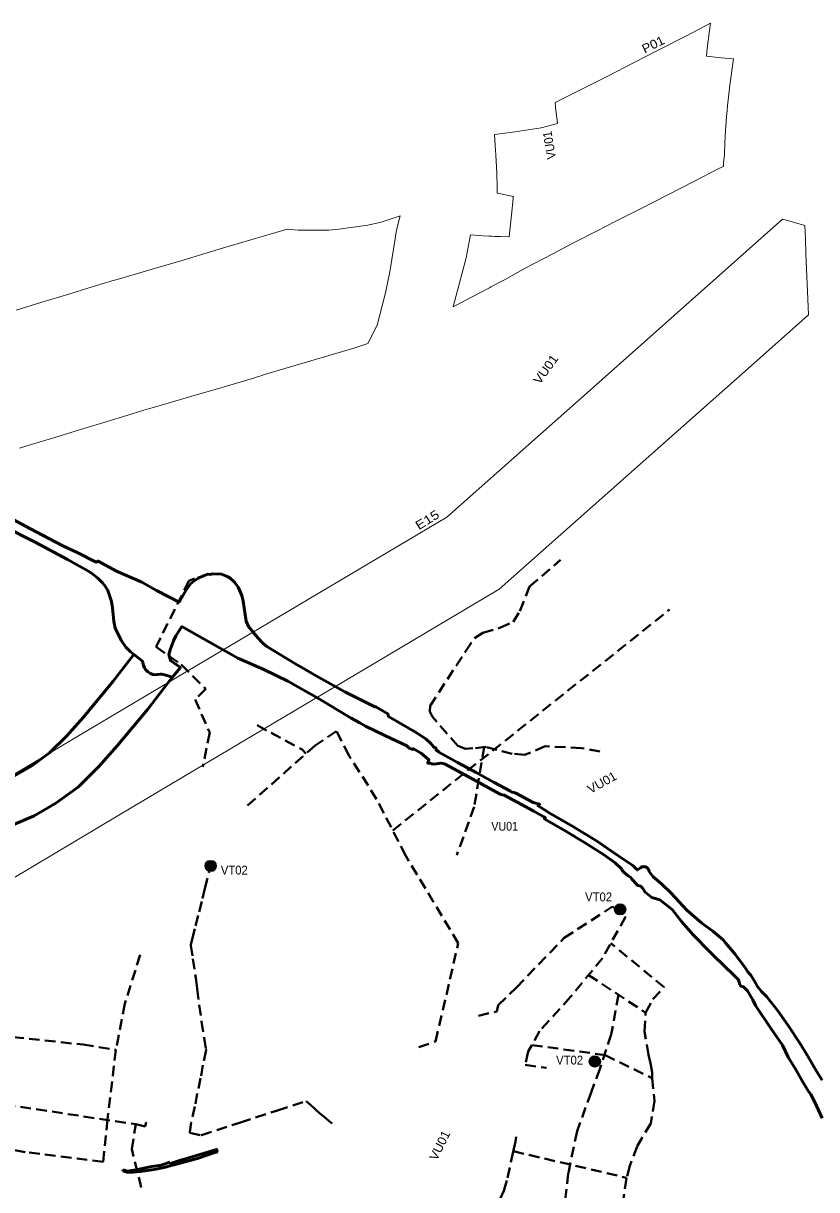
# Model space of a CAD drawing. Extents: x -650145 to -642675, y -1074338 to -1066724.
# Drawn here: x -646953 to -645166, y -1069896 to -1067267 of the extents above; entities that cross this region are included whole.
import ezdxf

# ---------------------------------------------------------------- set-up
doc = ezdxf.new("R2010")
doc.units = 0
doc.header["$LTSCALE"] = 8
doc.linetypes.add('MEDIUM_DASHED', pattern=[4.5, 3, -1.5])
for name, color, linetype, lineweight in [('12', 7, 'MEDIUM_DASHED', 40), ('15', 7, 'Continuous', 13), ('20', 7, 'Continuous', 13), ('44', 7, 'Continuous', 53), ('45', 7, 'Continuous', 53)]:
    doc.layers.add(name, color=color, linetype=linetype, lineweight=lineweight)
doc.layers.add('17', color=7, linetype='Continuous')
doc.layers.add('2', color=7, linetype='Continuous')

msp = doc.modelspace()

# ---------------------------------------------------------------- hatches: boundary and pattern name
at = {"layer": '15'}
for points in [[(-646519.621, -1069166.048, 1), (-646543.146, -1069166.048, 1)], [(-645597.068, -1069264.181, 1), (-645620.593, -1069264.181, 1)], [(-645654.023, -1069606.85, 1), (-645677.548, -1069606.85, 1)]]:
    msp.add_hatch(color=256, dxfattribs=at).paths.add_polyline_path(points)

# ---------------------------------------------------------------- linework, layer by layer
at = {"layer": '12'}
for p, q in [((-646121.289, -1069086.031), (-645497.437, -1068588.325)), ((-645679.959, -1069412.046), (-645551.493, -1069496.874)), ((-645849.328, -1069809.196), (-645594.304, -1069869.281))]:
    msp.add_line(p, q, dxfattribs=at)
for points in [[(-645654.382, -1068908.587), (-645695.934, -1068900.379), (-645777.633, -1068896.262), (-645823.286, -1068915.717), (-645852.103, -1068913.393), (-645911.131, -1068898.055), (-645940.704, -1068901.002), (-645957.145, -1068902.238), (-645974.835, -1068895.314), (-646031.512, -1068830.196), (-646037.554, -1068818.111), (-646037.089, -1068805.562), (-645957.124, -1068682.702), (-645937.201, -1068653.001), (-645917.947, -1068640.958), (-645880.242, -1068629.719), (-645849.757, -1068616.071), (-645834.514, -1068591.986), (-645812.854, -1068536.591), (-645743.059, -1068476.379)], [(-646567.712, -1068518.211), (-646580.293, -1068523.244), (-646654.473, -1068672.619), (-646597.568, -1068712.249), (-646542.696, -1068767.122), (-646566.575, -1068791.001), (-646533.55, -1068865.689), (-646548.767, -1068942.794)], [(-646062.183, -1069574.695), (-646024.736, -1069561.612), (-645973.562, -1069340.254), (-646092.013, -1069143.037), (-646157.557, -1069015.41), (-646220.085, -1068916.892), (-646248.016, -1068862.258), (-646295.932, -1068894.5), (-646451.322, -1069032.874)], [(-646426.669, -1068849.138), (-646325.196, -1068903.916), (-646316.818, -1068913.099)], [(-645915.285, -1068897.386), (-645937.63, -1069033.023), (-645976.999, -1069141.866)], [(-646576.25, -1069344.69), (-646576.07, -1069344.19), (-646572.92, -1069331.38), (-646565.43, -1069301.45), (-646557.53, -1069269.39), (-646550.09, -1069239.83), (-646544.34, -1069216.84), (-646534.934, -1069179.318)], [(-645927.806, -1069503.664), (-645886.806, -1069494.297), (-645883.788, -1069480.205), (-645842.55, -1069439.942), (-645734.927, -1069328.215), (-645626.154, -1069257.704), (-645596.435, -1069280.712), (-645648.533, -1069373.739), (-645720.378, -1069461.316), (-645790.62, -1069538.59), (-645815.779, -1069584.682), (-645822.696, -1069614.711), (-645775.097, -1069621.255)], [(-646576.25, -1069344.69), (-646576.14, -1069345.28), (-646571.6, -1069375.24), (-646565.13, -1069418.25), (-646561.67, -1069443.36), (-646557.02, -1069479.48), (-646551.76, -1069516.65), (-646546.19, -1069553.66), (-646542.189, -1069579.489), (-646541.86, -1069581.61), (-646548.99, -1069615.32), (-646554.11, -1069644.37), (-646561.65, -1069679.08), (-646567.03, -1069708.57), (-646575.01, -1069744.61), (-646578.22, -1069766.52), (-646578.238, -1069766.625), (-646578.433, -1069767.754), (-646552.777, -1069773.113), (-646552.12, -1069773.25), (-646464.51, -1069744.51), (-646380.87, -1069717.23), (-646346.59, -1069706.12), (-646316.394, -1069696.504), (-646316.32, -1069696.48), (-646306.32, -1069704.97), (-646296.979, -1069713.37), (-646296.125, -1069714.146), (-646285.929, -1069723.39), (-646275.84, -1069731.47), (-646264.46, -1069741.23), (-646257.888, -1069746.914)], [(-645807.67, -1069569.827), (-645642.853, -1069592.369), (-645537.006, -1069644.608), (-645537.068, -1069631.54), (-645540.509, -1069610.611), (-645545.036, -1069592.007), (-645553.718, -1069539.481), (-645551.493, -1069496.874), (-645535.107, -1069466.529), (-645509.579, -1069439.682), (-645629.872, -1069340.417)], [(-646690.349, -1069366.515), (-646724.478, -1069476.486), (-646744.903, -1069580.656)], [(-645612.686, -1069456.467), (-645628.75, -1069545.873), (-645654.668, -1069623.875), (-645674.387, -1069676.46), (-645706.032, -1069763.934), (-645725.616, -1069858.975), (-645736.083, -1069949.319)], [(-647047.983, -1069544.191), (-646818.857, -1069568.917), (-646744.903, -1069580.656), (-646763.998, -1069737.618), (-646773.775, -1069832.942), (-646949.668, -1069811.025), (-647072.241, -1069787.533)], [(-645537.006, -1069644.608), (-645531.552, -1069695.67), (-645540.071, -1069746.311), (-645570.504, -1069798.227), (-645587.257, -1069841.96), (-645594.542, -1069870.205), (-645609.199, -1069964.997), (-645695.3, -1069946.789), (-645735.674, -1069949.294), (-645761.611, -1069954.176), (-645786.679, -1069962.538), (-645837.185, -1069988.794), (-645851.6, -1069958.035), (-645886.355, -1069931.852)], [(-647279.5, -1069716.624), (-647208.318, -1069694.158), (-647143.504, -1069688.843), (-647066.866, -1069693.057), (-646699.975, -1069748.527), (-646678.869, -1069753.112), (-646676.91, -1069743.82)], [(-646687.702, -1069891.186), (-646709.186, -1069804.667), (-646700.4, -1069748.435)], [(-645906.816, -1070051.7), (-645897.34, -1070035.615), (-645902.834, -1069999.35), (-645901.735, -1069972.609), (-645895.874, -1069952.462), (-645870.943, -1069898.484), (-645862.678, -1069869.213), (-645849.656, -1069810.695), (-645844.459, -1069786.925), (-645843.101, -1069776.602)]]:
    msp.add_lwpolyline(points, dxfattribs=at)
at = {"layer": '15'}
for points in [[(-645405.461, -1067266.956), (-645459.124, -1067294.842), (-645523.1, -1067327.464), (-645578.654, -1067356.15), (-645636.938, -1067386.16), (-645755.627, -1067445.619), (-645754.45, -1067456.07), (-645749.67, -1067492.54), (-645786.52, -1067502.4), (-645845.49, -1067511.66), (-645891.61, -1067517.46), (-645890.8, -1067542.09), (-645888.69, -1067563.35), (-645886.5, -1067604.41), (-645886.3, -1067638)], [(-645353.76, -1067347.31), (-645381.01, -1067344.47), (-645414.55, -1067340.98), (-645412.77, -1067323.6), (-645407.69, -1067283.25), (-645405.461, -1067266.956)], [(-645360.9, -1067401.05), (-645358.77, -1067385.3), (-645356.48, -1067368.37), (-645354.97, -1067357.16), (-645353.76, -1067347.31)], [(-645366.91, -1067452.72), (-645363.1, -1067419.95), (-645361.48, -1067406.06), (-645360.9, -1067401.05)], [(-645369.16, -1067476.7), (-645367.93, -1067463.58), (-645366.91, -1067452.72)], [(-645371.73, -1067507.06), (-645371.09, -1067499.49), (-645369.16, -1067476.7)], [(-645374.09, -1067562.75), (-645373, -1067535.51), (-645372.51, -1067523.27), (-645371.73, -1067507.06)], [(-645376.157, -1067589.286), (-645375.63, -1067582.48), (-645374.09, -1067562.75)], [(-645984.712, -1067905.99), (-645926.226, -1067874.994), (-645903.512, -1067862.929), (-645901.047, -1067861.609), (-645900.008, -1067861.056), (-645869.73, -1067844.967), (-645822.534, -1067819.103), (-645761.702, -1067787.243), (-645713.714, -1067761.995), (-645660.64, -1067734.415), (-645619.713, -1067713.557), (-645563.205, -1067684.762), (-645501.082, -1067653.64), (-645441.166, -1067622.79), (-645386.14, -1067594.376), (-645376.157, -1067589.286)], [(-645886.3, -1067638), (-645886.24, -1067648.47), (-645886.23, -1067649.44), (-645886.23, -1067649.94), (-645849.48, -1067657.36), (-645849.52, -1067657.86), (-645849.92, -1067662.49)], [(-645849.92, -1067662.49), (-645850.48, -1067668.94), (-645851.81, -1067684.35), (-645858.82, -1067747.99), (-645892.22, -1067747.76), (-645917.73, -1067746.17), (-645946.03, -1067743.35), (-645949.27, -1067759.64), (-645955.97, -1067795.26), (-645984.712, -1067905.99)], [(-645917.73, -1067746.17), (-645858.82, -1067747.99), (-645853.346, -1067698.291), (-645849.92, -1067662.49)], [(-646137.4, -1067874.3), (-646127.7, -1067827.4), (-646118.8, -1067771.3), (-646113, -1067733.4), (-646104.6, -1067701), (-646147.4, -1067714.8), (-646177.7, -1067721.6), (-646215.6, -1067727), (-646241.8, -1067731), (-646265.3, -1067733), (-646282.66, -1067733.1), (-646334.1, -1067733.4), (-646359.237, -1067731.258), (-646492.002, -1067769.967)], [(-646492.002, -1067769.967), (-646504.961, -1067774.022), (-646529.365, -1067781.499), (-646593.13, -1067800.524), (-646658.06, -1067819.479), (-646742.053, -1067843.994), (-646753.887, -1067847.445), (-646755.382, -1067847.819), (-646771.25, -1067852.794), (-646807.854, -1067864.206), (-646850.892, -1067877.156), (-646911.586, -1067895.218), (-646969.855, -1067913.144)], [(-646409.773, -1068058.581), (-646208.581, -1067999.266), (-646177.649, -1067988.892), (-646156.3, -1067947.3), (-646137.4, -1067874.3)], [(-646962.367, -1068224.194), (-646945.867, -1068219.271), (-646882.405, -1068200.116), (-646824.694, -1068182.362), (-646764.888, -1068164.564), (-646719.986, -1068151.054), (-646681.73, -1068139.126), (-646671.337, -1068135.868), (-646658.027, -1068131.986), (-646574, -1068107.461), (-646508.21, -1068088.256), (-646442.535, -1068068.661), (-646416.219, -1068060.598), (-646409.773, -1068058.581)]]:
    msp.add_lwpolyline(points, dxfattribs=at)
at = {"layer": '15', "lineweight": 35}
for centre in [(-646531.383, -1069166.048), (-645608.83, -1069264.181), (-645665.785, -1069606.85)]:
    msp.add_circle(centre, 11.762, dxfattribs=at)
at = {"layer": '20'}
for points in [[(-646738.287, -1069051.902), (-646456.362, -1068884.319), (-646162.737, -1068709.771), (-645881.136, -1068542.25), (-645563.458, -1068260.279), (-645320.624, -1068044.744), (-645184.426, -1067923.894), (-645185.5, -1067905.76), (-645190.61, -1067785.41), (-645191.55, -1067752.42), (-645192.4, -1067722.74), (-645241.99, -1067708.63), (-645242.878, -1067708.378)], [(-645242.878, -1067708.378), (-645453.376, -1067895.156), (-645696.222, -1068110.701)], [(-645696.222, -1068110.701), (-645999.704, -1068380.07), (-646264.963, -1068537.869), (-646558.558, -1068712.401), (-646840.473, -1068879.978), (-647082.853, -1069024.029), (-647392.269, -1069006.02), (-647721.495, -1068986.72), (-648010.52, -1068969.88), (-648329.902, -1068951.251), (-648639.277, -1068933.111), (-648948.071, -1068915.071), (-649057.05, -1068908.69), (-649199.47, -1069030.73), (-649232.77, -1069060.44), (-649258.79, -1069091.17), (-649263.719, -1069096.97)], [(-649263.719, -1069096.97), (-648650.963, -1069132.769), (-648341.578, -1069150.909), (-648022.16, -1069169.54), (-647733.165, -1069186.38), (-647403.931, -1069205.68), (-647033.327, -1069227.251), (-646738.287, -1069051.902)]]:
    msp.add_lwpolyline(points, dxfattribs=at)
at = {"layer": '44'}
msp.add_line((-646729.54, -1069853.69), (-646729.24, -1069851.41), dxfattribs=at)
for points in [[(-646515.63, -1069810.24), (-646522.32, -1069812.28), (-646560.92, -1069825.33), (-646613.65, -1069840.02), (-646620.06, -1069841.69), (-646629.83, -1069844.23), (-646635.93, -1069845.82), (-646658.5, -1069850.59), (-646689.73, -1069854.58), (-646705.87, -1069856.62), (-646717.66, -1069857.11), (-646729.54, -1069853.69)], [(-646593.34, -1069827.68), (-646518.19, -1069805.27), (-646515.63, -1069810.24)], [(-646729.24, -1069851.41), (-646723.5, -1069852.83), (-646719.82, -1069853.78), (-646689.63, -1069849.7), (-646689.8, -1069848.71), (-646664.22, -1069843.72), (-646648.18, -1069841.04), (-646648.28, -1069841.78), (-646638.34, -1069838.73), (-646623.31, -1069834.1)], [(-646623.31, -1069834.1), (-646622.54, -1069835.88), (-646622.19, -1069836.71), (-646597.29, -1069828.86), (-646593.34, -1069827.68)]]:
    msp.add_lwpolyline(points, dxfattribs=at)
at = {"layer": '45'}
for points in [[(-646653.21, -1068545.58), (-646653.21, -1068545.58), (-646686.84, -1068526.89), (-646743.69, -1068501.76), (-646785.05, -1068479.12), (-646789.49, -1068481.31), (-646832.29, -1068460.04), (-646864.48, -1068444.64), (-646938.95, -1068405.8), (-647002.71, -1068371.09)], [(-646997.06, -1068401.37), (-646927.06, -1068436.66), (-646854.18, -1068475.8), (-646828.2, -1068489.61), (-646807.82, -1068501.17), (-646799.79, -1068506.39), (-646785.34, -1068517.77), (-646775.44, -1068527.74), (-646768.95, -1068535.8), (-646763.1, -1068545.18), (-646754.92, -1068569.81), (-646752.59, -1068584.55), (-646749.35, -1068615.18), (-646746.32, -1068630.23)], [(-645253.4, -1069493.06), (-645278.31, -1069461.33), (-645290.5, -1069449.03), (-645299.61, -1069437.97), (-645306.16, -1069425.55), (-645314.14, -1069412.54), (-645321.1, -1069405.21), (-645326.59, -1069396.64), (-645350.63, -1069363.98), (-645371.12, -1069339.47), (-645376.38, -1069332.65), (-645400.07, -1069313.32), (-645424.8, -1069295.24), (-645458.45, -1069265.56), (-645494.13, -1069227.63), (-645515.89, -1069206.66), (-645534.25, -1069190.56), (-645543.43, -1069178.39), (-645544.154, -1069175.682), (-645544.448, -1069174.993), (-645545.631, -1069172.966), (-645547.269, -1069171.107), (-645548.594, -1069170.034), (-645550.076, -1069169.141), (-645551.674, -1069168.459), (-645553.344, -1069168.007), (-645555.036, -1069167.793), (-645556.702, -1069167.808), (-645558.298, -1069168.035), (-645559.793, -1069168.445), (-645561.162, -1069169.007), (-645561.794, -1069169.334), (-645562.95, -1069170.06), (-645567.5, -1069173.46), (-645569.81, -1069175.03), (-645571.9, -1069173.43), (-645579.94, -1069165.52), (-645616.63, -1069140.8), (-645662.44, -1069109.89), (-645694.447, -1069089.98), (-645713.61, -1069078.06), (-645770.04, -1069045.34), (-645773.38, -1069043.46), (-645793.638, -1069031.021), (-645790.53, -1069027.19), (-645805.16, -1069023.52), (-645843.56, -1069002.41), (-645848.18, -1069000.48), (-645852.91, -1068999.62), (-645856.26, -1068997.79), (-645892.77, -1068977.86), (-645933.28, -1068955.74), (-645975.31, -1068932.8), (-646017.55, -1068909.75), (-646017.39, -1068908.42), (-646023.56, -1068905.05), (-646023.13, -1068903.12), (-646023.92, -1068900.73), (-646025.57, -1068899.39), (-646028.18, -1068898.89), (-646031.31, -1068894.32), (-646034.65, -1068891.12), (-646046.48, -1068879.92), (-646074.78, -1068861.51), (-646075.56, -1068861.95), (-646130.68, -1068829.21), (-646132.62, -1068823.54), (-646159.1, -1068807.43), (-646161.45, -1068807.54), (-646229.44, -1068773.53), (-646288.59, -1068740.88), (-646331.26, -1068716.25), (-646337.93, -1068712.4), (-646404.83, -1068671.52), (-646413.45, -1068664.71), (-646425.11, -1068652.37), (-646446.54, -1068626.14), (-646451.82, -1068614.31), (-646458.03, -1068569.26), (-646461.14, -1068556.34), (-646469.51, -1068538.15), (-646477.41, -1068526.45), (-646487.92, -1068516.87), (-646495.416, -1068512.888), (-646507.4, -1068508.45), (-646528.18, -1068507.58), (-646531.9, -1068509.25), (-646537.71, -1068508.16), (-646545.57, -1068511.42), (-646556.22, -1068515.84), (-646559.72, -1068517.29), (-646569.61, -1068524.1), (-646577.07, -1068530.2), (-646587.28, -1068545.28), (-646599.75, -1068566.49), (-646602.21, -1068571.5), (-646653.21, -1068545.58), (-646653.21, -1068545.58)], [(-646746.32, -1068630.23), (-646740.91, -1068642.34), (-646732.25, -1068659.06), (-646722.6, -1068673.11)], [(-646722.6, -1068673.11), (-646712.93, -1068683), (-646684.7, -1068704.95), (-646682.98, -1068714.07), (-646680.88, -1068719.28), (-646678.08, -1068723.7), (-646673.16, -1068728.69), (-646667.17, -1068732.38), (-646661.5, -1068734.35), (-646656.47, -1068735.13), (-646651.21, -1068734.99), (-646645.18, -1068733.91), (-646642.04, -1068733.74), (-646634.37, -1068735.27), (-646622.62, -1068739.32), (-646617.991, -1068741.503), (-646599.51, -1068718.755), (-646622.01, -1068703.3), (-646625.35, -1068689.7), (-646622.68, -1068678.75), (-646615.19, -1068659.11), (-646609.7, -1068647.84), (-646596.28, -1068626.52), (-646545.73, -1068654.81), (-646486.23, -1068688.54), (-646470.225, -1068697.579), (-646448.02, -1068707.99), (-646411.3, -1068723.11), (-646357.87, -1068749.64), (-646288.37, -1068789.04), (-646214.92, -1068832.85), (-646195.52, -1068843.92), (-646182.57, -1068851.3), (-646137.23, -1068872.6), (-646089.63, -1068895.5), (-646084.1, -1068900.51), (-646076.09, -1068903.48), (-646074.51, -1068901.9), (-646057.13, -1068911.62), (-646039.84, -1068926.67), (-646042.5, -1068933.91), (-646040.65, -1068934.59), (-646037.5, -1068934.7), (-646032.61, -1068936.1), (-646027.69, -1068936.6), (-646022.77, -1068936.12), (-646017.6, -1068934.89), (-646012.64, -1068934.34), (-646007.7, -1068935.18), (-646002.95, -1068936.95), (-645993.5, -1068942.1), (-645940.77, -1068970.74), (-645896.91, -1068994.75), (-645879.17, -1069004.02), (-645874.49, -1069005.73), (-645869.83, -1069006.45), (-645850.79, -1069016.84), (-645803.29, -1069042.92), (-645781.12, -1069055.29), (-645777.73, -1069057.2), (-645779.49, -1069059.92), (-645773.29, -1069063.99), (-645732.65, -1069086.82), (-645688.87, -1069113.44), (-645646.08, -1069140.37), (-645620.2, -1069159.26), (-645606.11, -1069172.98), (-645603.91, -1069176.86), (-645599, -1069181.48), (-645590.41, -1069189.45), (-645584.73, -1069191.88), (-645582.63, -1069195.88), (-645568.9, -1069209.87), (-645562.17, -1069212.02), (-645560.72, -1069214.25), (-645559.33, -1069214.54), (-645552.2, -1069225.59), (-645537.44, -1069237.41), (-645519.59, -1069242.38), (-645491.63, -1069264.25), (-645470.44, -1069291.24), (-645444.62, -1069321.35), (-645405.7, -1069360.27), (-645368.13, -1069397.37), (-645358.04, -1069406.84), (-645342.49, -1069423.06), (-645339.31, -1069433.27), (-645336.66, -1069437.47), (-645330.57, -1069438.89), (-645327.2, -1069442.53), (-645323.36, -1069445.79), (-645322.13, -1069447.96), (-645309.62, -1069467.79), (-645303.57, -1069480.49), (-645268.57, -1069533.23), (-645242.75, -1069570.26), (-645230.42, -1069597.39), (-645230.42, -1069597.39)], [(-646978.92, -1069073.93), (-646929.186, -1069052.925), (-646880.163, -1069024.903), (-646829.104, -1068987.917), (-646782.784, -1068941.581), (-646741.85, -1068895.719), (-646673.05, -1068812.491), (-646618.655, -1068742.359), (-646617.991, -1068741.503), (-646622.62, -1068739.32), (-646634.37, -1068735.27), (-646642.04, -1068733.74), (-646645.18, -1068733.91), (-646651.21, -1068734.99), (-646656.47, -1068735.13), (-646661.5, -1068734.35), (-646667.17, -1068732.38), (-646673.16, -1068728.69), (-646678.08, -1068723.7), (-646680.88, -1068719.28), (-646682.98, -1068714.07), (-646684.7, -1068704.95), (-646704.316, -1068689.698), (-646725.374, -1068716.786), (-646751.116, -1068749.975), (-646817.718, -1068830.545), (-646855.506, -1068872.883), (-646894.206, -1068911.595), (-646934.465, -1068940.759), (-646973.61, -1068963.135)], [(-645153.33, -1069649.24), (-645166.67, -1069629), (-645184.88, -1069596.58), (-645202.56, -1069568.23), (-645230.1, -1069525.98), (-645253.4, -1069493.06)], [(-645230.42, -1069597.39), (-645214.76, -1069622.37), (-645198.41, -1069650.49), (-645185.17, -1069673.38), (-645179.12, -1069681.3), (-645170.3, -1069698.91), (-645153.44, -1069734.71)]]:
    msp.add_lwpolyline(points, dxfattribs=at)

# ---------------------------------------------------------------- texts
at = {"layer": '17', "width": 1.1}
msp.add_text('P01', height=20, rotation=26.08, dxfattribs=at).set_placement((-645553.682, -1067335.106))
at = {"layer": '17', "width": 0.95}
for p in [(-646508.55, -1069185.576), (-645687.853, -1069245.943), (-645753.107, -1069613.825)]:
    msp.add_text('VT02', height=20, dxfattribs=at).set_placement(p)
at = {"layer": '2'}
for rotation, width, p in [(99.44, 0.95, (-645753.336, -1067571.35)), (54.217, 1.1, (-645789.911, -1068082.457)), (29.327, 1.05, (-645675.485, -1069004.004)), (63.768, 1.05, (-646021.976, -1069831.992))]:
    msp.add_text('VU01', height=20, rotation=rotation, dxfattribs=dict(at, width=width)).set_placement(p)
at = {"layer": '2', "width": 0.9}
msp.add_text('VU01', height=20, dxfattribs=at).set_placement((-645899.102, -1069086.768))
at = {"layer": '20', "width": 1.2}
msp.add_text('E15', height=20, rotation=31.922, dxfattribs=at).set_placement((-646062.368, -1068409.739))

doc.saveas('drawing.dxf')
